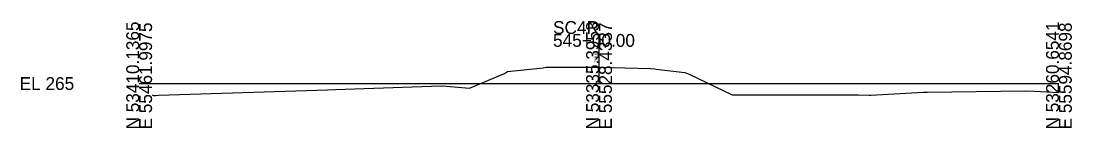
# Model space of a CAD drawing. Extents: x 7498 to 13027, y 90095 to 109625.
# Drawn here: x 10498.3 to 10726.8, y 95095.5 to 95118.8 of the extents above; entities that cross this region are included whole.
import ezdxf

# ---------------------------------------------------------------- set-up
doc = ezdxf.new("R2010")
doc.units = 0
for name, color, linetype in [('Level 10', 7, 'Continuous'), ('Level 60', 7, 'Continuous'), ('Level 63', 7, 'Continuous')]:
    doc.layers.add(name, color=color, linetype=linetype)

msp = doc.modelspace()

# ---------------------------------------------------------------- linework, layer by layer
at = {"layer": 'Level 60'}
for p, q in [((10604.06, 95107.76), (10611.86, 95108.59)), ((10611.86, 95108.59), (10612.51, 95108.7)), ((10612.51, 95108.7), (10613.46, 95108.7)), ((10613.46, 95108.7), (10624, 95108.76)), ((10624, 95108.76), (10635.15, 95108.41)), ((10635.15, 95108.41), (10636.09, 95108.38)), ((10636.09, 95108.38), (10636.42, 95108.31)), ((10636.42, 95108.31), (10642.66, 95107.58)), ((10595.85, 95104.17), (10603.41, 95107.32)), ((10603.41, 95107.32), (10604.06, 95107.76)), ((10642.66, 95107.58), (10643.76, 95107.13)), ((10643.76, 95107.13), (10652.96, 95102.72)), ((10528.23, 95102.61), (10564.94, 95103.8)), ((10564.94, 95103.8), (10566.66, 95103.83)), ((10566.66, 95103.83), (10587.56, 95104.57)), ((10587.56, 95104.57), (10589.95, 95104.64)), ((10589.95, 95104.64), (10595.85, 95104.17)), ((10695.44, 95103.27), (10716.55, 95103.54)), ((10716.55, 95103.54), (10717.04, 95103.5)), ((10717.04, 95103.5), (10717.37, 95103.55)), ((10717.37, 95103.55), (10723.99, 95103.22)), ((10526.8, 95102.72), (10527.11, 95102.59)), ((10527.11, 95102.59), (10527.57, 95102.54)), ((10527.57, 95102.54), (10528.23, 95102.61)), ((10652.96, 95102.72), (10680.37, 95102.7)), ((10680.37, 95102.7), (10682.79, 95102.62)), ((10682.79, 95102.62), (10683.11, 95102.62)), ((10683.11, 95102.62), (10694.46, 95103.27)), ((10694.46, 95103.27), (10695.44, 95103.27))]:
    msp.add_line(p, q, dxfattribs=at)
at = {"layer": 'Level 63'}
for p, q in [((10623.99, 95105.16), (10623.99, 95115.97)), ((10523.99, 95105.16), (10623.99, 95105.16)), ((10623.99, 95105.16), (10723.99, 95105.16))]:
    msp.add_line(p, q, dxfattribs=at)

# ---------------------------------------------------------------- texts
at = {"layer": 'Level 10'}
msp.add_text('268.60', height=0.6, rotation=90, dxfattribs=at).set_placement((10623.59, 95109.76))
at = {"layer": 'Level 63'}
for s, p in [('N 53410.1365', (10523.99, 95095.16)), ('E 55461.9975', (10526.79, 95095.16)), ('N 53335.3953', (10623.99, 95095.16)), ('E 55528.4337', (10626.79, 95095.16)), ('N 53260.6541', (10723.99, 95095.16)), ('E 55594.8698', (10726.79, 95095.16))]:
    msp.add_text(s, height=2.8, rotation=90, dxfattribs=at).set_placement(p)
for s, p in [('SC4R', (10613.99, 95115.97)), ('545+00.00', (10613.99, 95113.17)), ('EL 265', (10498, 95103.76))]:
    msp.add_text(s, height=2.8, dxfattribs=at).set_placement(p)

doc.saveas('drawing.dxf')
